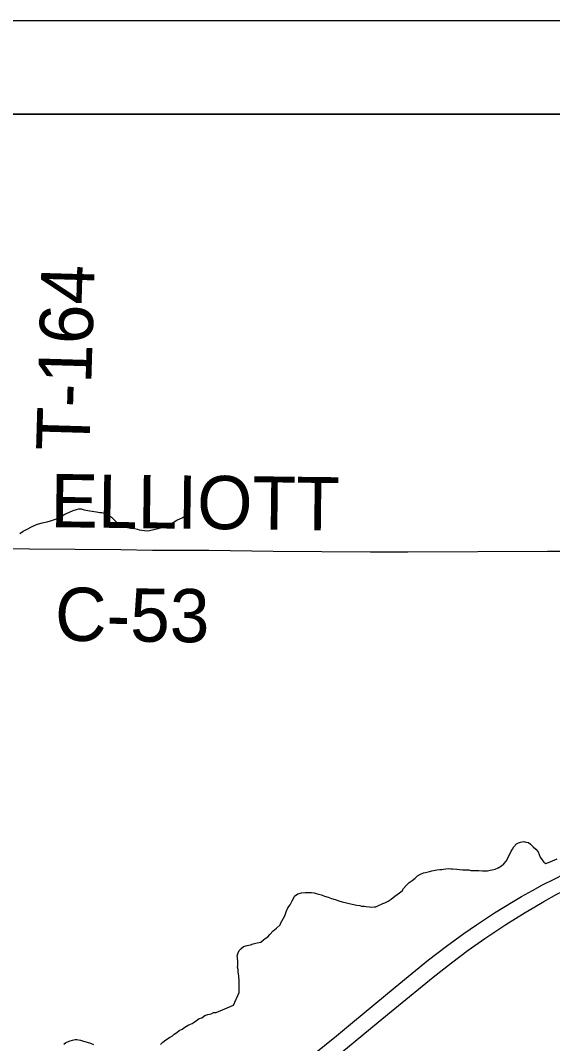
# Model space of a CAD drawing. Extents: x 0 to 34, y 0 to 22.
# Drawn here: x 26.927 to 27.494, y 19.908 to 21 of the extents above; entities that cross this region are included whole.
import ezdxf

# ---------------------------------------------------------------- set-up
doc = ezdxf.new("R2010")
doc.units = 0
for name, color, linetype in [('GM_X_County_Road', 7, 'Continuous'), ('GM_X_County_Road_Text', 7, 'Continuous'), ('GM_X_Minor_River', 7, 'Continuous'), ('GM_X_Township_Road', 7, 'Continuous'), ('GM_X_Township_Road_Text', 7, 'Continuous'), ('GM_X_US_Route', 7, 'Continuous'), ('SH_Data', 7, 'Continuous')]:
    doc.layers.add(name, color=color, linetype=linetype)

msp = doc.modelspace()

# ---------------------------------------------------------------- linework, layer by layer
at = {"layer": 'GM_X_County_Road'}
msp.add_lwpolyline([(26.8985, 20.4364), (26.9042, 20.4364), (26.9365, 20.4363), (27.0341, 20.4354), (27.0677, 20.4349), (27.128, 20.4346), (27.1964, 20.4338), (27.3002, 20.4328), (27.34, 20.4329), (27.4892, 20.4336), (27.5569, 20.4337)], dxfattribs=at)
at = {"layer": 'GM_X_Minor_River'}
for points in [[(26.9264, 20.4525), (26.9298, 20.4551), (26.9341, 20.4572), (26.9387, 20.4598), (26.9441, 20.4623), (26.9502, 20.464), (26.9555, 20.465), (26.959, 20.4661), (26.9621, 20.4671), (26.9655, 20.4682), (26.9674, 20.4689), (26.9705, 20.4707), (26.9744, 20.4733), (26.9794, 20.4754), (26.9832, 20.4772), (26.9866, 20.4783), (26.9893, 20.479), (26.9916, 20.4789), (26.995, 20.4777), (27.001, 20.4768), (27.0082, 20.4755), (27.0116, 20.475), (27.0139, 20.4749), (27.0166, 20.4741), (27.0184, 20.4737), (27.0218, 20.4713), (27.024, 20.4698), (27.0303, 20.4639), (27.0337, 20.4627), (27.036, 20.4611), (27.0382, 20.4599), (27.0412, 20.4591), (27.0446, 20.4582), (27.0488, 20.4577), (27.0518, 20.4573), (27.0537, 20.4565), (27.0564, 20.456), (27.0594, 20.4556), (27.0628, 20.4555), (27.0678, 20.4565), (27.0708, 20.4572), (27.0739, 20.4579), (27.0773, 20.4589), (27.0808, 20.46), (27.0831, 20.4607), (27.0862, 20.4625), (27.09, 20.4643), (27.0939, 20.4668), (27.0977, 20.4686), (27.0996, 20.4694), (27.1035, 20.4719), (27.1054, 20.473), (27.1054, 20.4726), (27.1054, 20.473)], [(27.3763, 20.0939), (27.3782, 20.0943), (27.3805, 20.0946), (27.3839, 20.0949), (27.3858, 20.0948), (27.3877, 20.0947), (27.3923, 20.0942), (27.3953, 20.0941), (27.3983, 20.0937), (27.401, 20.0936), (27.4033, 20.0935), (27.4052, 20.0935), (27.4074, 20.093), (27.4101, 20.093), (27.4127, 20.0929), (27.4158, 20.0928), (27.4196, 20.0927), (27.4218, 20.0926), (27.4249, 20.0925), (27.4279, 20.0932), (27.4302, 20.0935), (27.4333, 20.0942), (27.4364, 20.0956), (27.4399, 20.0978), (27.4426, 20.1), (27.4449, 20.103), (27.4465, 20.1052), (27.4474, 20.1079), (27.449, 20.1105), (27.4498, 20.1127), (27.4518, 20.1157), (27.453, 20.118), (27.4561, 20.1213), (27.458, 20.1224), (27.4603, 20.1231), (27.4638, 20.1237), (27.4661, 20.1233), (27.4687, 20.1228), (27.4709, 20.1209), (27.4739, 20.1181), (27.4765, 20.1158), (27.479, 20.113), (27.4801, 20.11), (27.4812, 20.1073), (27.483, 20.1045), (27.4852, 20.1018), (27.4874, 20.1002), (27.4901, 20.1013), (27.4943, 20.1031), (27.4993, 20.1052)], [(27.1542, 19.9492), (27.1601, 19.9626), (27.1602, 19.9645), (27.1603, 19.9668), (27.1603, 19.969), (27.1604, 19.9717), (27.1601, 19.974), (27.1601, 19.9763), (27.1598, 19.9786), (27.1599, 19.9805), (27.1596, 19.9824), (27.1593, 19.9846), (27.1593, 19.9873), (27.1586, 19.9896), (27.1587, 19.9915), (27.1588, 19.9953), (27.1586, 19.9999), (27.1582, 20.0018), (27.1591, 20.0052), (27.1603, 20.0074), (27.1619, 20.0093), (27.165, 20.0118), (27.1688, 20.0129), (27.1723, 20.0135), (27.1753, 20.0146), (27.1795, 20.0156), (27.1814, 20.0159), (27.1834, 20.0166), (27.1861, 20.0188), (27.188, 20.0203), (27.1907, 20.0221), (27.1931, 20.0247), (27.1966, 20.0284), (27.2001, 20.0314), (27.204, 20.035), (27.2048, 20.0369), (27.2061, 20.0395), (27.2077, 20.0422), (27.2089, 20.0444), (27.2105, 20.0489), (27.2122, 20.0531), (27.2145, 20.0564), (27.2157, 20.0583), (27.2169, 20.0605), (27.2181, 20.0631), (27.2194, 20.0654), (27.2228, 20.068), (27.2267, 20.069), (27.2305, 20.0693), (27.2335, 20.0695), (27.2354, 20.0695), (27.2373, 20.0694), (27.2404, 20.069), (27.2422, 20.0682), (27.2449, 20.0677), (27.2479, 20.0668), (27.2513, 20.0656), (27.255, 20.0644), (27.2588, 20.0631), (27.2626, 20.0619), (27.2667, 20.0606), (27.2701, 20.0594), (27.2746, 20.0585), (27.2776, 20.0576), (27.2856, 20.0559), (27.289, 20.0554), (27.2908, 20.055), (27.2935, 20.0549), (27.2958, 20.0545), (27.2992, 20.054), (27.3018, 20.0539), (27.3041, 20.0542), (27.306, 20.0542), (27.3095, 20.056), (27.3114, 20.0567), (27.3133, 20.0577), (27.3156, 20.0584), (27.3191, 20.0602), (27.3222, 20.0624), (27.3261, 20.0654), (27.3288, 20.0672), (27.3311, 20.069), (27.3339, 20.0712), (27.3355, 20.0738), (27.3382, 20.0768), (27.3417, 20.0801), (27.3448, 20.0823), (27.3479, 20.0849), (27.3503, 20.0871), (27.3537, 20.0889), (27.3568, 20.0903), (27.3591, 20.0906), (27.3633, 20.092), (27.3656, 20.0927), (27.3691, 20.0934), (27.371, 20.0937), (27.3744, 20.094), (27.3763, 20.0939)], [(27.0763, 19.9073), (27.079, 19.9096), (27.0821, 19.9121), (27.0859, 19.9147), (27.089, 19.9165), (27.091, 19.9184), (27.0937, 19.9202), (27.0964, 19.922), (27.0995, 19.9235), (27.1022, 19.9257), (27.106, 19.9279), (27.1083, 19.9289), (27.1103, 19.9296), (27.1122, 19.9311), (27.1149, 19.9329), (27.1176, 19.9348), (27.1203, 19.9358), (27.1238, 19.938), (27.1268, 19.9391), (27.1303, 19.9401), (27.133, 19.9412), (27.1356, 19.9415), (27.1542, 19.9492)], [(26.9733, 19.9077), (26.9753, 19.9092), (26.9772, 19.9102), (26.9799, 19.9113), (26.9826, 19.912), (26.9852, 19.9127), (26.9871, 19.9126), (26.989, 19.9122), (26.9909, 19.9118), (26.9932, 19.911), (27.0018, 19.9085), (27.0048, 19.9073)]]:
    msp.add_lwpolyline(points, dxfattribs=at)
at = {"layer": 'GM_X_Township_Road'}
msp.add_lwpolyline([(28.9104, 20.9), (23.5167, 20.9)], dxfattribs=at)
at = {"layer": 'GM_X_US_Route'}
msp.add_line((27.2639, 19.9166), (27.281, 19.9308), dxfattribs=at)
for points in [[(27.281, 19.9308), (27.3266, 19.9683), (27.3623, 19.9974), (27.3813, 20.0123), (27.3997, 20.0257), (27.4133, 20.035), (27.4327, 20.0477), (27.4524, 20.0598), (27.4615, 20.0651), (27.4729, 20.0716), (27.4839, 20.0775), (27.4955, 20.0833), (27.5079, 20.0896), (27.5261, 20.0988), (27.5482, 20.1079), (27.5592, 20.1128), (27.5713, 20.118), (27.5836, 20.1226), (27.5996, 20.1281), (27.616, 20.1332), (27.6259, 20.1362), (27.6353, 20.1386), (27.6438, 20.1404)], [(27.3084, 19.931), (27.3263, 19.9457), (27.3673, 19.979), (27.3867, 19.9945), (27.4046, 20.008), (27.4224, 20.0205), (27.4447, 20.0352), (27.4652, 20.0481), (27.4738, 20.0531), (27.485, 20.0599), (27.4991, 20.0675), (27.5186, 20.077), (27.5374, 20.0854), (27.5609, 20.0952), (27.5783, 20.102), (27.6001, 20.1094), (27.6209, 20.116), (27.6351, 20.1202), (27.6435, 20.1225)], [(27.1334, 19.7873), (27.1397, 19.7926), (27.1472, 19.7984), (27.2037, 19.845), (27.2445, 19.8785), (27.2544, 19.8865), (27.2758, 19.904), (27.3084, 19.931)], [(27.1346, 19.8123), (27.1839, 19.852), (27.253, 19.9076), (27.2639, 19.9166)]]:
    msp.add_lwpolyline(points, dxfattribs=at)
at = {"layer": 'SH_Data'}
for points in [[(23.4167, 21), (30.4167, 21), (30.4167, 14), (23.4167, 14)], [(23.5167, 20.9), (30.3167, 20.9), (30.3167, 14.1), (23.5167, 14.1)]]:
    msp.add_lwpolyline(points, close=True, dxfattribs=at)

# ---------------------------------------------------------------- texts
at = {"layer": 'GM_X_County_Road_Text'}
for s, rotation, p in [('ELLIOTT', 359.3329, (26.9588, 20.4593)), ('C-53', 359.3144, (26.9636, 20.3382))]:
    msp.add_text(s, height=0.05682, rotation=rotation, dxfattribs=at).set_placement(p)
at = {"layer": 'GM_X_Township_Road_Text'}
msp.add_text('T-164', height=0.05682, rotation=88.3151, dxfattribs=at).set_placement((27.0004, 20.5401))

doc.saveas('drawing.dxf')
